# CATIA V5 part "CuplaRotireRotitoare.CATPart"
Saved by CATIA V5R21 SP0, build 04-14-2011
Part number: stalp de rotatie
Material "Steel": density 7860 kg/m3, Young's modulus 2e+11 Pa, Poisson ratio 0.266, thermal expansion 1.17e-05 1/K
Bounding box of the stored display mesh (mm): x -60 to 60, y -60 to 60, z 0 to 498
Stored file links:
  C:\Users\MIRCEA\Desktop\PRRO\CATIAV5\CuplaRotireRotitoare.CATPart
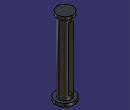
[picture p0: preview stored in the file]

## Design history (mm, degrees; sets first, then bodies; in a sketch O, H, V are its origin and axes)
Body1 (main body), material "Steel"
  Sketch1 on xy-plane, origin (0, 0, 0), H (1, 0, 0), V (0, 1, 0)
    circle A1 centre (0, 0) radius 60
    radius A1 = 60
  Pad1: profile Sketch1, direction (0, 0, 1), length 20
  Plane1: type Offset, RefPlane xy-plane, Offset 20
  Sketch2 on Plane1, origin (0, 0, 20), H (1, 0, 0), V (0, 1, 0)
    circle A1 centre (0, 0) radius 40
    radius A1 = 40
  Pad2: profile Sketch2, direction (0, 0, 1), length 458
  Plane2: type Offset, RefPlane Plane1, Offset 458
  Sketch3 on Plane2, origin (0, 0, 478), H (1, 0, 0), V (0, 1, 0)
    circle A1 centre (0, 0) radius 50
    radius A1 = 50
  Pad3: profile Sketch3, direction (0, 0, 1), length 20
  Sketch4 on zx-plane, origin (0, 0, 0), H (-1, 0, 0), V (0, 0, 1)
    line L1 (15, 454) -> (15, 44)
    line L2 (15, 44) -> (-15, 44)
    line L3 (-15, 44) -> (-15, 454)
    line L4 (-15, 454) -> (15, 454)
    distance L2 L4 = 410
    distance L1 L3 = 30
    vertical: L1 V, L3 V
    horizontal: L2 H, L4 H
  Pocket1: profile Sketch4, direction (0, -1, 0), through (limit type 6)
  Pocket2: profile Sketch4, direction (0, 1, 0), through (limit type 6)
